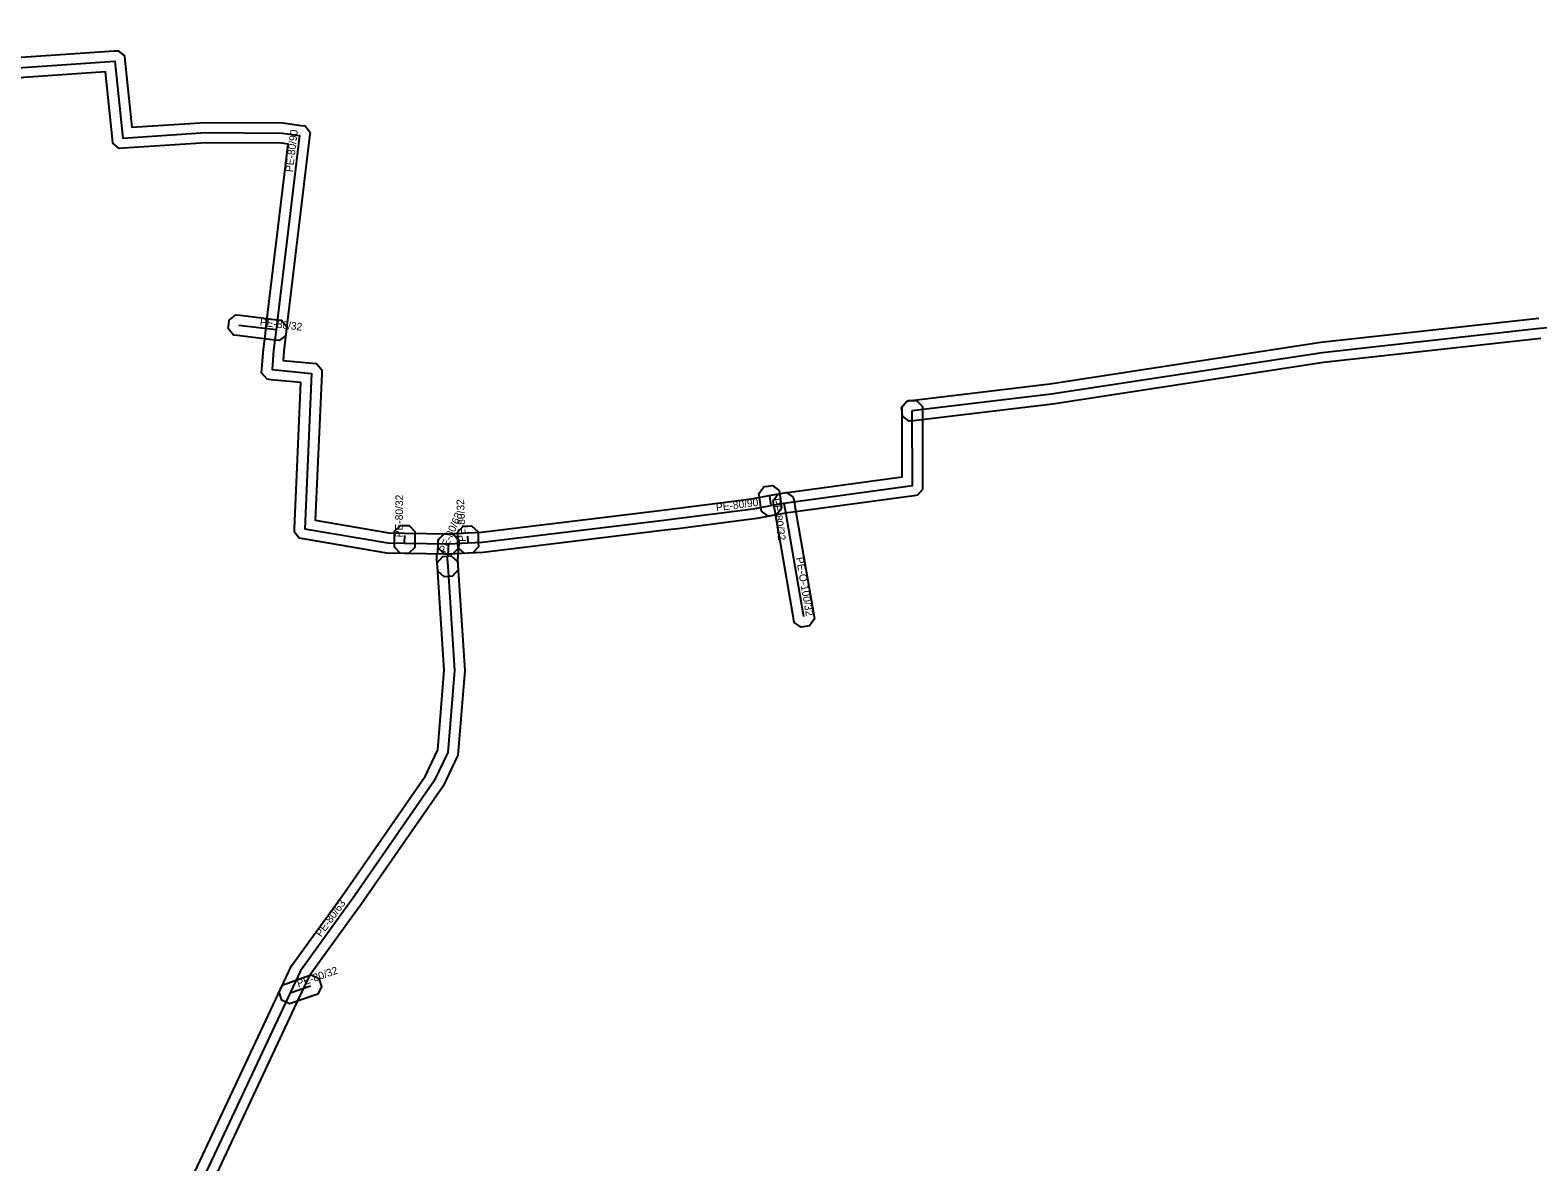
# Model space of a CAD drawing. Extents: x -569373 to -565022, y -1135090 to -1131496.
# Drawn here: x -567805.9 to -567658, y -1134151 to -1134039.9 of the extents above; entities that cross this region are included whole.
import ezdxf

# ---------------------------------------------------------------- set-up
doc = ezdxf.new("R2010")
doc.units = 0
for name, color, linetype in [('1', 7, 'Continuous'), ('24', 7, 'Continuous'), ('30', 7, 'Continuous')]:
    doc.layers.add(name, color=color, linetype=linetype)

msp = doc.modelspace()

# ---------------------------------------------------------------- linework, layer by layer
at = {"layer": '1'}
for points in [[(-567811.142, -1134042.848), (-567797.708, -1134041.932), (-567797.305, -1134041.905), (-567796.687, -1134042.425), (-567796.645, -1134042.827), (-567795.964, -1134049.419), (-567788.72, -1134048.94), (-567781.137, -1134048.99), (-567779.583, -1134049.209), (-567779.365, -1134049.239), (-567778.959, -1134049.294), (-567778.458, -1134049.943), (-567778.507, -1134050.35), (-567780.807, -1134069.428), (-567780.867, -1134069.938), (-567781.045, -1134071.41), (-567781.115, -1134072.298), (-567778.225, -1134072.575), (-567777.827, -1134072.613), (-567777.303, -1134073.215), (-567777.321, -1134073.614), (-567777.952, -1134087.991), (-567770.737, -1134089.212), (-567769.173, -1134089.24), (-567764.864, -1134089.31), (-567764.45, -1134089.317), (-567763.873, -1134089.912), (-567763.88, -1134090.326), (-567763.887, -1134090.74), (-567764.482, -1134091.317), (-567764.896, -1134091.31), (-567769.207, -1134091.24), (-567770.923, -1134091.208), (-567779.157, -1134089.816), (-567779.53, -1134089.753), (-567780.006, -1134089.164), (-567779.989, -1134088.786), (-567779.361, -1134074.475), (-567782.285, -1134074.195), (-567782.693, -1134074.156), (-567783.219, -1134073.529), (-567783.187, -1134073.121), (-567783.035, -1134071.21), (-567782.853, -1134069.702), (-567782.793, -1134069.192), (-567780.61, -1134051.085), (-567781.283, -1134050.99), (-567788.66, -1134050.94), (-567796.794, -1134051.478), (-567797.197, -1134051.504), (-567797.814, -1134050.984), (-567797.855, -1134050.583), (-567798.535, -1134043.993), (-567810.838, -1134044.832)], [(-567657.675, -1134070.146), (-567678.999, -1134072.502), (-567705.594, -1134076.581), (-567719.241, -1134078.223), (-567719.652, -1134078.272), (-567720.303, -1134077.76), (-567720.353, -1134077.349), (-567720.402, -1134076.938), (-567719.89, -1134076.287), (-567719.479, -1134076.237), (-567705.866, -1134074.599), (-567679.261, -1134070.518), (-567657.865, -1134068.154)], [(-567792.488, -1134157.737), (-567781.336, -1134133.956), (-567780.285, -1134131.71), (-567775.979, -1134125.772), (-567775.106, -1134124.571), (-567767.149, -1134113.068), (-567765.932, -1134110.506), (-567765.293, -1134102.712), (-567765.958, -1134092.565), (-567765.985, -1134092.152), (-567765.438, -1134091.529), (-567765.025, -1134091.502), (-567764.612, -1134091.475), (-567763.989, -1134092.022), (-567763.962, -1134092.435), (-567763.287, -1134102.728), (-567763.968, -1134111.034), (-567765.411, -1134114.072), (-567773.474, -1134125.729), (-567774.361, -1134126.948), (-567778.555, -1134132.73), (-567779.524, -1134134.804), (-567790.732, -1134158.703)]]:
    msp.add_lwpolyline(points, dxfattribs=at)
for points in [[(-567781.508, -1134070.352), (-567781.919, -1134070.303), (-567785.579, -1134069.863), (-567785.99, -1134069.813), (-567786.502, -1134069.162), (-567786.453, -1134068.751), (-567786.403, -1134068.34), (-567785.752, -1134067.828), (-567785.341, -1134067.877), (-567781.681, -1134068.317), (-567781.27, -1134068.367), (-567780.758, -1134069.018), (-567780.807, -1134069.429), (-567780.857, -1134069.84)], [(-567765.34, -1134089.33), (-567764.927, -1134089.311), (-567762.998, -1134089.221), (-567761.646, -1134089.153), (-567743.601, -1134086.957), (-567742.614, -1134086.838), (-567735.895, -1134085.979), (-567734.933, -1134085.839), (-567733.408, -1134085.56), (-567732.108, -1134085.322), (-567720.351, -1134083.717), (-567720.36, -1134077.231), (-567720.36, -1134076.817), (-567719.775, -1134076.23), (-567719.361, -1134076.23), (-567718.947, -1134076.23), (-567718.36, -1134076.815), (-567718.36, -1134077.229), (-567718.35, -1134084.589), (-567718.35, -1134084.964), (-567718.843, -1134085.53), (-567719.215, -1134085.581), (-567731.792, -1134087.298), (-567733.048, -1134087.528), (-567734.609, -1134087.813), (-567735.625, -1134087.961), (-567742.366, -1134088.822), (-567743.359, -1134088.943), (-567761.474, -1134091.147), (-567762.902, -1134091.219), (-567764.833, -1134091.309), (-567765.247, -1134091.328), (-567765.86, -1134090.77), (-567765.879, -1134090.357), (-567765.898, -1134089.943)], [(-567732.428, -1134085.069), (-567732.37, -1134085.479), (-567732.238, -1134086.403), (-567732.18, -1134086.813), (-567732.677, -1134087.476), (-567733.087, -1134087.534), (-567733.497, -1134087.592), (-567734.16, -1134087.095), (-567734.218, -1134086.685), (-567734.35, -1134085.761), (-567734.408, -1134085.351), (-567733.911, -1134084.688), (-567733.501, -1134084.63), (-567733.091, -1134084.572)], [(-567731.037, -1134085.728), (-567730.965, -1134086.136), (-567730.845, -1134086.818), (-567729.068, -1134097.067), (-567729.034, -1134097.261), (-567728.964, -1134097.669), (-567729.443, -1134098.346), (-567729.851, -1134098.416), (-567730.259, -1134098.486), (-567730.936, -1134098.007), (-567731.006, -1134097.599), (-567731.038, -1134097.407), (-567732.815, -1134087.162), (-567732.935, -1134086.484), (-567733.007, -1134086.076), (-567732.532, -1134085.397), (-567732.124, -1134085.325), (-567731.716, -1134085.253)], [(-567770.195, -1134090.64), (-567770.19, -1134090.226), (-567770.18, -1134089.486), (-567770.174, -1134089.072), (-567769.58, -1134088.495), (-567769.166, -1134088.5), (-567768.752, -1134088.506), (-567768.175, -1134089.1), (-567768.18, -1134089.514), (-567768.19, -1134090.254), (-567768.196, -1134090.668), (-567768.79, -1134091.245), (-567769.204, -1134091.24), (-567769.618, -1134091.234)], [(-567763.93, -1134090.679), (-567763.949, -1134090.265), (-567763.979, -1134089.605), (-567763.998, -1134089.191), (-567763.439, -1134088.58), (-567763.025, -1134088.561), (-567762.611, -1134088.542), (-567762, -1134089.101), (-567761.981, -1134089.515), (-567761.951, -1134090.175), (-567761.932, -1134090.589), (-567762.491, -1134091.2), (-567762.905, -1134091.219), (-567763.319, -1134091.238)], [(-567766.03, -1134091.384), (-567765.937, -1134091.171), (-567765.878, -1134090.246), (-567765.851, -1134089.833), (-567765.229, -1134089.286), (-567764.816, -1134089.312), (-567764.403, -1134089.339), (-567763.856, -1134089.961), (-567763.882, -1134090.374), (-567763.963, -1134091.649), (-567764.01, -1134091.756), (-567763.962, -1134092.431), (-567763.933, -1134092.844), (-567764.478, -1134093.469), (-567764.891, -1134093.498), (-567765.304, -1134093.527), (-567765.929, -1134092.982), (-567765.958, -1134092.569), (-567766.008, -1134091.838)], [(-567781.148, -1134133.571), (-567780.757, -1134133.435), (-567778.737, -1134132.735), (-567778.346, -1134132.6), (-567777.601, -1134132.962), (-567777.465, -1134133.353), (-567777.33, -1134133.744), (-567777.692, -1134134.489), (-567778.083, -1134134.625), (-567780.103, -1134135.325), (-567780.494, -1134135.46), (-567781.239, -1134135.098), (-567781.375, -1134134.707), (-567781.51, -1134134.316)]]:
    msp.add_lwpolyline(points, close=True, dxfattribs=at)
at = {"layer": '24'}
for points in [[(-567817.76, -1134039.89), (-567815.95, -1134045.03), (-567810.99, -1134043.84), (-567797.64, -1134042.93), (-567796.86, -1134050.48), (-567788.69, -1134049.94), (-567781.21, -1134049.99), (-567779.72, -1134050.2), (-567779.5, -1134050.23), (-567781.8, -1134069.31), (-567781.86, -1134069.82), (-567782.04, -1134071.31), (-567782.19, -1134073.2), (-567778.32, -1134073.57), (-567778.99, -1134088.83), (-567770.83, -1134090.21), (-567769.19, -1134090.24), (-567764.88, -1134090.31)], [(-567719.36, -1134077.23), (-567705.73, -1134075.59), (-567679.13, -1134071.51), (-567657.77, -1134069.15), (-567638.31, -1134067.58), (-567634.41, -1134067.42), (-567598.85, -1134066.05), (-567573.55, -1134065.01), (-567560.7, -1134064.7), (-567544.89, -1134065.77), (-567536.07, -1134067.12), (-567527.09, -1134068.94), (-567518.11, -1134071.28), (-567510.5, -1134073.74), (-567501.14, -1134077.14), (-567499.52, -1134077.67), (-567487.74, -1134082.76), (-567478.65, -1134087.36), (-567460.455, -1134096.721)], [(-567781.8, -1134069.31), (-567785.46, -1134068.87)], [(-567764.88, -1134090.31), (-567762.95, -1134090.22), (-567761.56, -1134090.15), (-567743.48, -1134087.95), (-567742.49, -1134087.83), (-567735.76, -1134086.97), (-567734.771, -1134086.826), (-567733.228, -1134086.544), (-567731.95, -1134086.31), (-567719.35, -1134084.59), (-567719.36, -1134077.23)], [(-567733.36, -1134085.62), (-567733.228, -1134086.544)], [(-567731.95, -1134086.31), (-567731.83, -1134086.99), (-567730.053, -1134097.237), (-567730.02, -1134097.43)], [(-567769.19, -1134090.24), (-567769.18, -1134089.5)], [(-567764.88, -1134090.31), (-567764.95, -1134091.41), (-567765.02, -1134091.57), (-567765.01, -1134091.78), (-567764.96, -1134092.5)], [(-567762.95, -1134090.22), (-567762.98, -1134089.56)], [(-567764.96, -1134092.5), (-567764.29, -1134102.72), (-567764.95, -1134110.77), (-567766.28, -1134113.57), (-567774.29, -1134125.15), (-567775.17, -1134126.36), (-567779.42, -1134132.22), (-567780.43, -1134134.38), (-567791.61, -1134158.22), (-567795.81, -1134164.81)], [(-567780.43, -1134134.38), (-567778.41, -1134133.68)]]:
    msp.add_lwpolyline(points, dxfattribs=at)

# ---------------------------------------------------------------- texts
at = {"layer": '30'}
for s, rotation, p in [('PE-80/90', 83.12644, (-567780.161, -1134053.853)), ('PE-80/32', 353.14488, (-567783.43, -1134068.89)), ('PE-80/32', 89.22578, (-567769.385, -1134089.67)), ('PE-80/90', 7.28213, (-567738.576, -1134087.104)), ('PE-80/32', 278.1301, (-567733.094, -1134085.882)), ('PE-80/63', 66.37062, (-567765.171, -1134091.258)), ('PE-80/32', 92.60256, (-567763.165, -1134090.09)), ('PE-O-100/32', 279.8382, (-567730.784, -1134091.67)), ('PE-80/63', 54.04828, (-567777.388, -1134128.942)), ('PE-80/32', 19.11297, (-567779.62, -1134133.83))]:
    msp.add_text(s, height=0.75, rotation=rotation, dxfattribs=at).set_placement(p)

doc.saveas('drawing.dxf')
